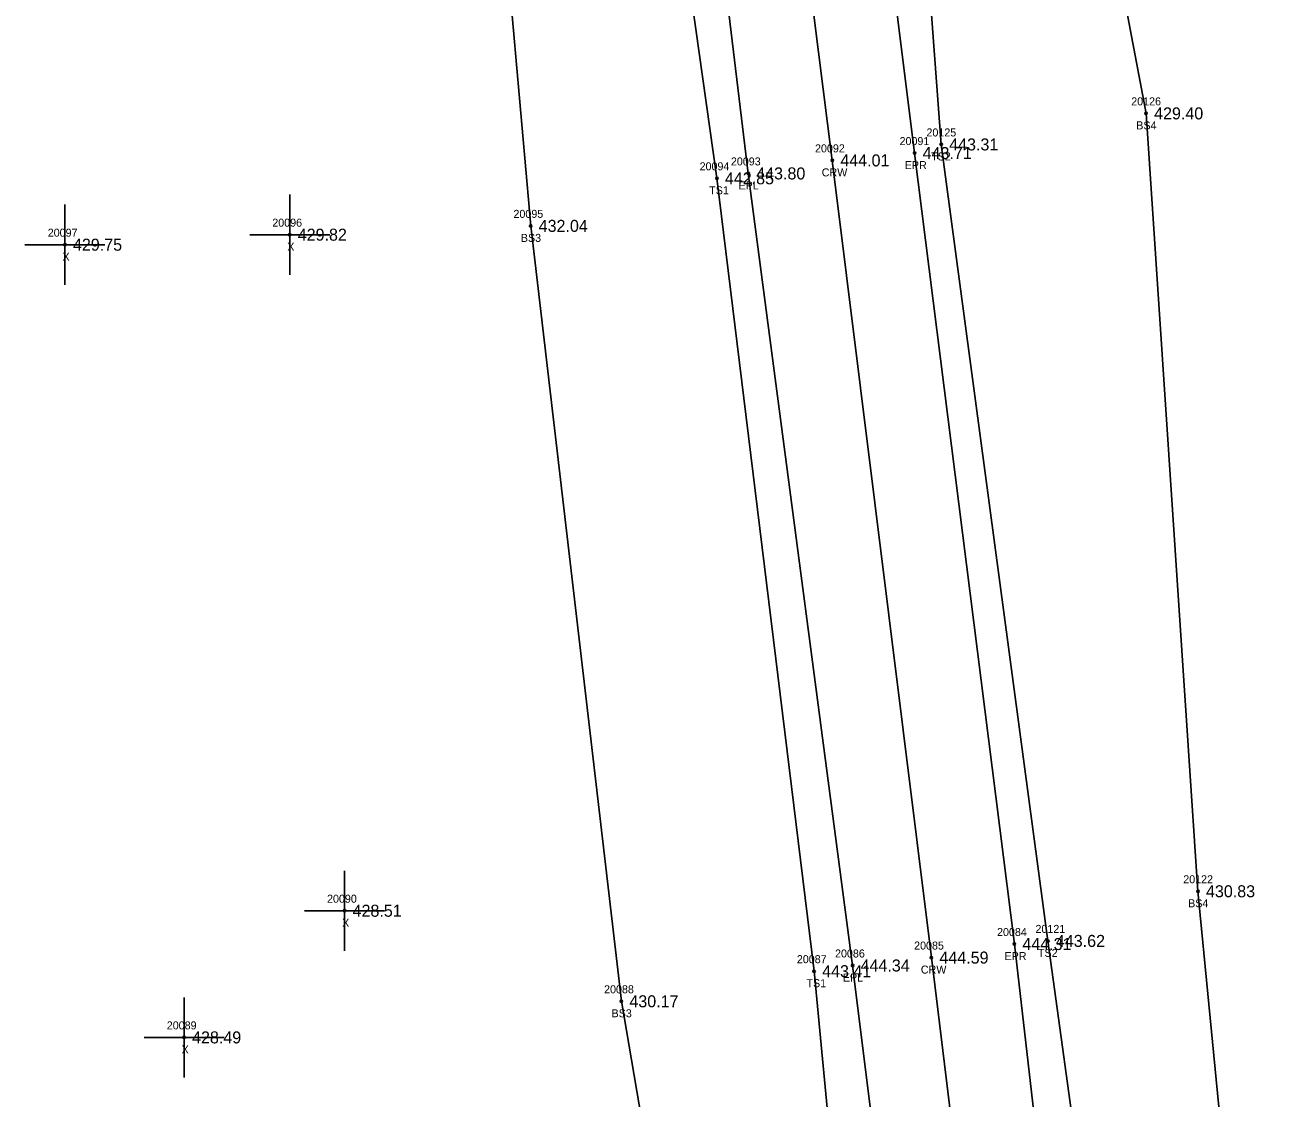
# Model space of a CAD drawing. Extents: x 1858461 to 1858936, y 1147060 to 1148183.
# Drawn here: x 1858553.6 to 1858709.6, y 1147742.4 to 1147876.4 of the extents above; entities that cross this region are included whole.
import ezdxf

# ---------------------------------------------------------------- set-up
doc = ezdxf.new("R2010")
doc.units = 0
for name, color, linetype in [('RD_DTM_BkLn1', 7, 'Continuous'), ('RD_DTM_BkLn2', 7, 'Continuous'), ('RD_DTM_BkLn_txCode', 7, 'Continuous'), ('RD_EX_Misc', 7, 'Continuous'), ('RD_EX_Misc_txCode', 7, 'Continuous'), ('RD_EX_Road', 7, 'Continuous'), ('RD_EX_Road_txCode', 7, 'Continuous'), ('RD_EX_TX_Misc_ELEV', 7, 'Continuous'), ('RD_EX_TX_Road_ELEV', 7, 'Continuous'), ('RD_HC_Survey_ELEV', 7, 'Continuous'), ('RD_HC_Survey_txCode', 7, 'Continuous'), ('RD_SMD_Locator', 7, 'Continuous')]:
    doc.layers.add(name, color=color, linetype=linetype)

msp = doc.modelspace()

# ---------------------------------------------------------------- linework, layer by layer
at = {"layer": 'RD_DTM_BkLn1'}
msp.add_lwpolyline([(1858679.02, 1147660.19), (1858666.85, 1147759.91), (1858654.47, 1147859.47), (1858641.87, 1147959.15), (1858630.02, 1148056.08), (1858617.26, 1148157.44)], dxfattribs=at)
at = {"layer": 'RD_DTM_BkLn2'}
for points in [[(1858693.62, 1147653.8), (1858703.51, 1147658.34), (1858709.65, 1147670.29), (1858700.15, 1147768.19), (1858693.67, 1147865.34), (1858675.79, 1147959.77), (1858663.27, 1148067), (1858650.31, 1148162.46)], [(1858691.24, 1147663), (1858693.74, 1147672.32), (1858681.4, 1147761.99), (1858668.07, 1147861.46), (1858660.68, 1147960.55), (1858649.11, 1148060.84), (1858635.41, 1148160.22)], [(1858693.62, 1147653.8), (1858663.6, 1147639.15), (1858647.78, 1147639.17), (1858628.12, 1147754.45), (1858616.79, 1147851.29), (1858607.32, 1147958.26), (1858596.73, 1148053.14), (1858583.42, 1148154.64)], [(1858665.51, 1147658.67), (1858661.09, 1147664.96), (1858652.2, 1147758.21), (1858640.05, 1147857.23), (1858625.95, 1147957.13), (1858612.72, 1148055.44), (1858600.29, 1148155.52)]]:
    msp.add_lwpolyline(points, dxfattribs=at)
at = {"layer": 'RD_EX_Misc'}
for p, q in [((1858586.69, 1147845.19), (1858586.69, 1147855.19)), ((1858558.61, 1147843.94), (1858558.61, 1147853.94)), ((1858553.61, 1147848.94), (1858563.61, 1147848.94)), ((1858581.69, 1147850.19), (1858591.69, 1147850.19)), ((1858593.54, 1147760.76), (1858593.54, 1147770.76)), ((1858588.54, 1147765.76), (1858598.54, 1147765.76)), ((1858573.49, 1147744.94), (1858573.49, 1147754.94)), ((1858568.49, 1147749.94), (1858578.49, 1147749.94))]:
    msp.add_line(p, q, dxfattribs=at)
at = {"layer": 'RD_EX_Road'}
for points in [[(1858679.02, 1147660.19), (1858688.73, 1147661.54), (1858677.21, 1147761.6), (1858664.75, 1147860.38), (1858652.33, 1147959.9), (1858640.18, 1148058.71), (1858627.63, 1148158.94)], [(1858679.02, 1147660.19), (1858669.49, 1147658.82), (1858657, 1147758.92), (1858643.96, 1147857.84), (1858631.87, 1147958), (1858619.69, 1148055.49), (1858606.59, 1148156.75)]]:
    msp.add_lwpolyline(points, dxfattribs=at)
at = {"layer": 'RD_SMD_Locator'}
for centre in [(1858693.67, 1147865.34), (1858668.07, 1147861.46), (1858664.75, 1147860.38), (1858654.47, 1147859.47), (1858640.05, 1147857.23), (1858643.96, 1147857.84), (1858616.79, 1147851.29), (1858558.61, 1147848.94), (1858586.69, 1147850.19), (1858700.15, 1147768.19), (1858593.54, 1147765.76), (1858677.21, 1147761.6), (1858681.4, 1147761.99), (1858666.85, 1147759.91), (1858652.2, 1147758.21), (1858657, 1147758.92), (1858628.12, 1147754.45), (1858573.49, 1147749.94)]:
    msp.add_circle(centre, 0.15, dxfattribs=at)

# ---------------------------------------------------------------- texts
at = {"layer": 'RD_DTM_BkLn_txCode'}
for s, p in [('20126', (1858691.81, 1147866.34)), ('20125', (1858666.23, 1147862.46)), ('BS4', (1858692.44, 1147863.34)), ('TS2', (1858666.82, 1147859.46)), ('20094', (1858637.89, 1147858.23)), ('TS1', (1858639.09, 1147855.23)), ('20095', (1858614.64, 1147852.29)), ('BS3', (1858615.56, 1147849.29)), ('20122', (1858698.31, 1147769.19)), ('BS4', (1858698.92, 1147766.19)), ('20121', (1858679.85, 1147762.99)), ('20087', (1858650.04, 1147759.21)), ('TS2', (1858680.16, 1147759.99)), ('TS1', (1858651.24, 1147756.21)), ('20088', (1858625.96, 1147755.45)), ('BS3', (1858626.89, 1147752.45))]:
    msp.add_text(s, height=1, dxfattribs=at).set_placement(p)
at = {"layer": 'RD_EX_Misc_txCode'}
for s, p in [('20096', (1858584.51, 1147851.19)), ('20097', (1858556.46, 1147849.94)), ('X', (1858586.38, 1147848.19)), ('X', (1858558.3, 1147846.94)), ('20090', (1858591.35, 1147766.76)), ('X', (1858593.23, 1147763.76)), ('20089', (1858571.33, 1147750.94)), ('X', (1858573.18, 1147747.94))]:
    msp.add_text(s, height=1, dxfattribs=at).set_placement(p)
at = {"layer": 'RD_EX_Road_txCode'}
for s, p in [('20091', (1858662.87, 1147861.38)), ('20093', (1858641.8, 1147858.84)), ('EPR', (1858663.52, 1147858.38)), ('EPL', (1858642.75, 1147855.84)), ('20084', (1858675.05, 1147762.6)), ('20086', (1858654.81, 1147759.92)), ('EPR', (1858675.98, 1147759.6)), ('EPL', (1858655.79, 1147756.92))]:
    msp.add_text(s, height=1, dxfattribs=at).set_placement(p)
at = {"layer": 'RD_EX_TX_Misc_ELEV'}
for s, p in [('429.40', (1858694.67, 1147864.59)), ('443.31', (1858669.07, 1147860.71)), ('442.85', (1858641.05, 1147856.48)), ('432.04', (1858617.79, 1147850.54)), ('429.82', (1858587.69, 1147849.44)), ('429.75', (1858559.61, 1147848.19)), ('430.83', (1858701.15, 1147767.44)), ('428.51', (1858594.54, 1147765.01)), ('443.62', (1858682.4, 1147761.24)), ('443.41', (1858653.2, 1147757.46)), ('430.17', (1858629.12, 1147753.7)), ('428.49', (1858574.49, 1147749.19))]:
    msp.add_text(s, height=1.5, dxfattribs=at).set_placement(p)
at = {"layer": 'RD_EX_TX_Road_ELEV'}
for s, p in [('443.71', (1858665.75, 1147859.63)), ('443.80', (1858644.96, 1147857.09)), ('444.31', (1858678.21, 1147760.85)), ('444.34', (1858658, 1147758.17))]:
    msp.add_text(s, height=1.5, dxfattribs=at).set_placement(p)
at = {"layer": 'RD_HC_Survey_ELEV'}
for s, p in [('444.01', (1858655.47, 1147858.72)), ('444.59', (1858667.85, 1147759.16))]:
    msp.add_text(s, height=1.5, dxfattribs=at).set_placement(p)
at = {"layer": 'RD_HC_Survey_txCode'}
for s, p in [('20092', (1858652.31, 1147860.47)), ('CRW', (1858653.15, 1147857.47)), ('20085', (1858664.69, 1147760.91)), ('CRW', (1858665.53, 1147757.91))]:
    msp.add_text(s, height=1, dxfattribs=at).set_placement(p)

doc.saveas('drawing.dxf')
